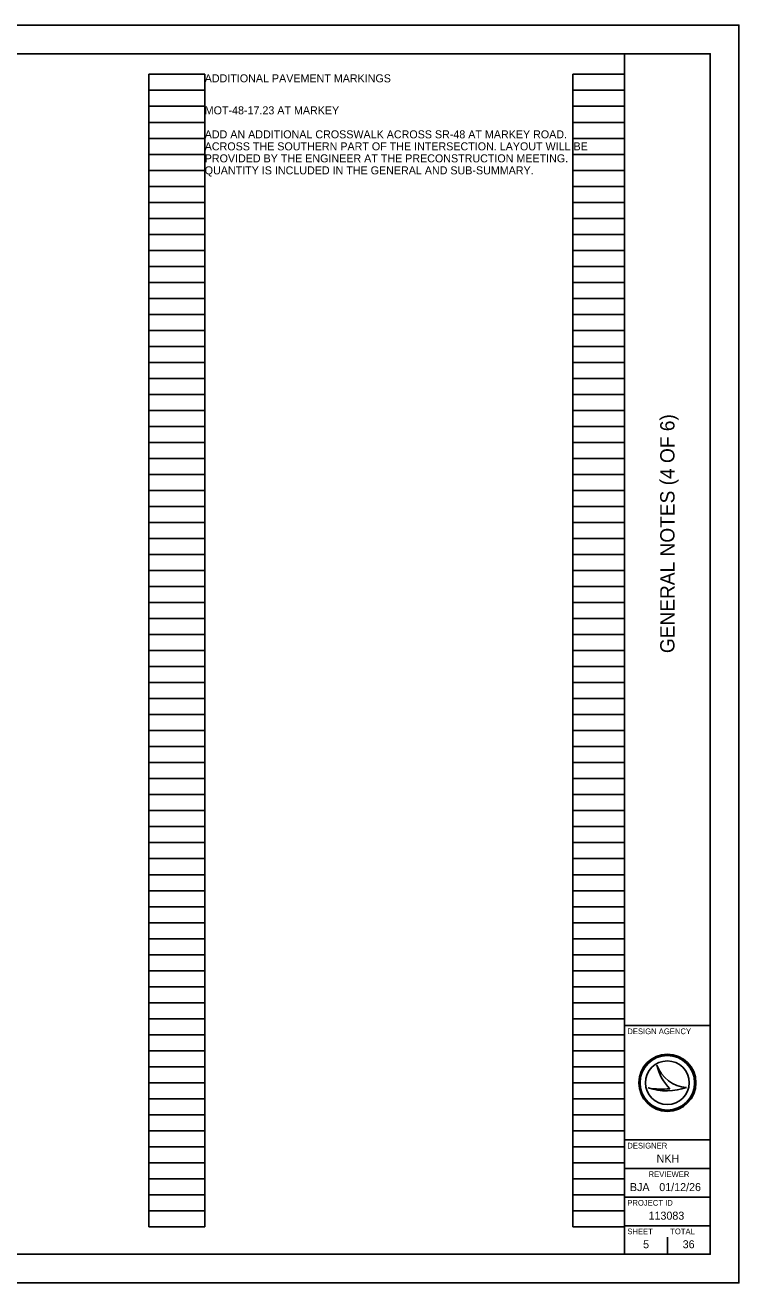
# Model space of a CAD drawing. Extents: x -27.4 to 34, y 0 to 22.
# Drawn here: x 21.52 to 34, y 0 to 22 of the extents above; entities that cross this region are included whole.
import ezdxf

# ---------------------------------------------------------------- set-up
doc = ezdxf.new("R2010")
doc.units = 0
for name, color, linetype in [('Default', 7, 'Continuous'), ('SH_Border', 7, 'Continuous'), ('SH_Cut_Line', 7, 'Continuous'), ('SH_Data', 7, 'Continuous')]:
    doc.layers.add(name, color=color, linetype=linetype)

msp = doc.modelspace()

# ---------------------------------------------------------------- linework, layer by layer
at = {"layer": 'Default'}
msp.add_line((1.5, 21.5), (24.949, 21.5), dxfattribs=at)
at = {"layer": 'SH_Border'}
for p, q in [((32, 0.5), (32, 21.5)), ((32, 4.5), (33.5, 4.5)), ((32, 2.5), (33.5, 2.5)), ((32, 2), (33.5, 2)), ((32, 1.5), (33.5, 1.5)), ((32, 1), (33.5, 1))]:
    msp.add_line(p, q, dxfattribs=at)
msp.add_lwpolyline([(1.5, 21.5), (33.5, 21.5), (33.5, 0.5), (1.5, 0.5)], close=True, dxfattribs=at)
at = {"layer": 'SH_Cut_Line'}
msp.add_lwpolyline([(0, 0), (34, 0), (34, 22), (0, 22)], close=True, dxfattribs=at)
at = {"layer": 'SH_Data'}
for p, q in [((23.68, 0.98), (23.68, 21.14)), ((23.68, 21.14), (24.66, 21.14)), ((24.66, 0.98), (24.66, 21.14)), ((31.1, 0.98), (31.1, 21.14)), ((31.1, 21.14), (32, 21.14)), ((32, 0.98), (32, 21.14)), ((23.68, 20.86), (24.66, 20.86)), ((31.1, 20.86), (32, 20.86)), ((23.68, 20.58), (24.66, 20.58)), ((31.1, 20.58), (32, 20.58)), ((23.68, 20.3), (24.66, 20.3)), ((31.1, 20.3), (32, 20.3)), ((23.68, 20.02), (24.66, 20.02)), ((31.1, 20.02), (32, 20.02)), ((23.68, 19.74), (24.66, 19.74)), ((31.1, 19.74), (32, 19.74)), ((23.68, 19.46), (24.66, 19.46)), ((31.1, 19.46), (32, 19.46)), ((23.68, 19.18), (24.66, 19.18)), ((31.1, 19.18), (32, 19.18)), ((23.68, 18.9), (24.66, 18.9)), ((31.1, 18.9), (32, 18.9)), ((23.68, 18.62), (24.66, 18.62)), ((31.1, 18.62), (32, 18.62)), ((23.68, 18.34), (24.66, 18.34)), ((31.1, 18.34), (32, 18.34)), ((23.68, 18.06), (24.66, 18.06)), ((31.1, 18.06), (32, 18.06)), ((23.68, 17.78), (24.66, 17.78)), ((31.1, 17.78), (32, 17.78)), ((23.68, 17.5), (24.66, 17.5)), ((31.1, 17.5), (32, 17.5)), ((23.68, 17.22), (24.66, 17.22)), ((31.1, 17.22), (32, 17.22)), ((23.68, 16.94), (24.66, 16.94)), ((31.1, 16.94), (32, 16.94)), ((23.68, 16.66), (24.66, 16.66)), ((31.1, 16.66), (32, 16.66)), ((23.68, 16.38), (24.66, 16.38)), ((31.1, 16.38), (32, 16.38)), ((23.68, 16.1), (24.66, 16.1)), ((31.1, 16.1), (32, 16.1)), ((23.68, 15.82), (24.66, 15.82)), ((31.1, 15.82), (32, 15.82)), ((23.68, 15.54), (24.66, 15.54)), ((31.1, 15.54), (32, 15.54)), ((23.68, 15.26), (24.66, 15.26)), ((31.1, 15.26), (32, 15.26)), ((23.68, 14.98), (24.66, 14.98)), ((31.1, 14.98), (32, 14.98)), ((23.68, 14.7), (24.66, 14.7)), ((31.1, 14.7), (32, 14.7)), ((23.68, 14.42), (24.66, 14.42)), ((31.1, 14.42), (32, 14.42)), ((23.68, 14.14), (24.66, 14.14)), ((31.1, 14.14), (32, 14.14)), ((23.68, 13.86), (24.66, 13.86)), ((31.1, 13.86), (32, 13.86)), ((23.68, 13.58), (24.66, 13.58)), ((31.1, 13.58), (32, 13.58)), ((23.68, 13.3), (24.66, 13.3)), ((31.1, 13.3), (32, 13.3)), ((23.68, 13.02), (24.66, 13.02)), ((31.1, 13.02), (32, 13.02)), ((23.68, 12.74), (24.66, 12.74)), ((31.1, 12.74), (32, 12.74)), ((23.68, 12.46), (24.66, 12.46)), ((31.1, 12.46), (32, 12.46)), ((23.68, 12.18), (24.66, 12.18)), ((31.1, 12.18), (32, 12.18)), ((23.68, 11.9), (24.66, 11.9)), ((31.1, 11.9), (32, 11.9)), ((23.68, 11.62), (24.66, 11.62)), ((31.1, 11.62), (32, 11.62)), ((23.68, 11.34), (24.66, 11.34)), ((31.1, 11.34), (32, 11.34)), ((23.68, 11.06), (24.66, 11.06)), ((31.1, 11.06), (32, 11.06)), ((23.68, 10.78), (24.66, 10.78)), ((31.1, 10.78), (32, 10.78)), ((23.68, 10.5), (24.66, 10.5)), ((31.1, 10.5), (32, 10.5)), ((23.68, 10.22), (24.66, 10.22)), ((31.1, 10.22), (32, 10.22)), ((23.68, 9.94), (24.66, 9.94)), ((31.1, 9.94), (32, 9.94)), ((23.68, 9.66), (24.66, 9.66)), ((31.1, 9.66), (32, 9.66)), ((23.68, 9.38), (24.66, 9.38)), ((31.1, 9.38), (32, 9.38)), ((23.68, 9.1), (24.66, 9.1)), ((31.1, 9.1), (32, 9.1)), ((23.68, 8.82), (24.66, 8.82)), ((31.1, 8.82), (32, 8.82)), ((23.68, 8.54), (24.66, 8.54)), ((31.1, 8.54), (32, 8.54)), ((23.68, 8.26), (24.66, 8.26)), ((31.1, 8.26), (32, 8.26)), ((23.68, 7.98), (24.66, 7.98)), ((31.1, 7.98), (32, 7.98)), ((23.68, 7.7), (24.66, 7.7)), ((31.1, 7.7), (32, 7.7)), ((23.68, 7.42), (24.66, 7.42)), ((31.1, 7.42), (32, 7.42)), ((23.68, 7.14), (24.66, 7.14)), ((31.1, 7.14), (32, 7.14)), ((23.68, 6.86), (24.66, 6.86)), ((31.1, 6.86), (32, 6.86)), ((23.68, 6.58), (24.66, 6.58)), ((31.1, 6.58), (32, 6.58)), ((23.68, 6.3), (24.66, 6.3)), ((31.1, 6.3), (32, 6.3)), ((23.68, 6.02), (24.66, 6.02)), ((31.1, 6.02), (32, 6.02)), ((23.68, 5.74), (24.66, 5.74)), ((31.1, 5.74), (32, 5.74)), ((23.68, 5.46), (24.66, 5.46)), ((31.1, 5.46), (32, 5.46)), ((23.68, 5.18), (24.66, 5.18)), ((31.1, 5.18), (32, 5.18)), ((23.68, 4.9), (24.66, 4.9)), ((31.1, 4.9), (32, 4.9)), ((23.68, 4.62), (24.66, 4.62)), ((31.1, 4.62), (32, 4.62)), ((23.68, 4.34), (24.66, 4.34)), ((31.1, 4.34), (32, 4.34)), ((23.68, 4.06), (24.66, 4.06)), ((31.1, 4.06), (32, 4.06)), ((23.68, 3.78), (24.66, 3.78)), ((31.1, 3.78), (32, 3.78)), ((32.567, 3.81), (32.567, 3.81)), ((23.68, 3.5), (24.66, 3.5)), ((31.1, 3.5), (32, 3.5)), ((32.417, 3.41), (32.417, 3.41)), ((32.75, 3.5), (32.75, 3.5)), ((33.087, 3.419), (33.087, 3.419)), ((23.68, 3.22), (24.66, 3.22)), ((31.1, 3.22), (32, 3.22)), ((23.68, 2.94), (24.66, 2.94)), ((31.1, 2.94), (32, 2.94)), ((23.68, 2.66), (24.66, 2.66)), ((31.1, 2.66), (32, 2.66)), ((23.68, 2.38), (24.66, 2.38)), ((31.1, 2.38), (32, 2.38)), ((23.68, 2.1), (24.66, 2.1)), ((31.1, 2.1), (32, 2.1)), ((23.68, 1.82), (24.66, 1.82)), ((31.1, 1.82), (32, 1.82)), ((23.68, 1.54), (24.66, 1.54)), ((31.1, 1.54), (32, 1.54)), ((23.68, 1.26), (24.66, 1.26)), ((31.1, 1.26), (32, 1.26)), ((23.68, 0.98), (24.66, 0.98)), ((31.1, 0.98), (32, 0.98)), ((32.375, 0.675), (32.375, 0.675)), ((32.75, 0.5), (32.75, 0.8))]:
    msp.add_line(p, q, dxfattribs=at)
for radius in [0.5, 0.477, 0.477, 0.382]:
    msp.add_circle((32.75, 3.5), radius, dxfattribs=at)
for centre, radius, start, end in [((33.116, 3.998), 0.58, 198.9257, 198.9319), ((33.347, 3.97), 0.796, 191.6379, 191.6421), ((33.116, 3.998), 0.58, 198.9319, 267.1657), ((33.347, 3.97), 0.796, 191.6421, 226.0947), ((32.739, 4.37), 1.013, 251.4576, 290.0832), ((32.648, 4.654), 1.266, 259.4964, 259.4995), ((32.739, 4.37), 1.013, 251.4527, 251.4576), ((32.648, 4.654), 1.266, 259.4995, 276.6672)]:
    msp.add_arc(centre, radius, start, end, dxfattribs=at)

# ---------------------------------------------------------------- texts
at = {"layer": 'Default'}
for s, p in [('ADDITIONAL PAVEMENT MARKINGS', (24.66, 21)), ('MOT-48-17.23 AT MARKEY', (24.66, 20.44)), ('ADD AN ADDITIONAL CROSSWALK ACROSS SR-48 AT MARKEY ROAD. ', (24.66, 20.02)), ('ACROSS THE SOUTHERN PART OF THE INTERSECTION. LAYOUT WILL BE ', (24.66, 19.81)), ('PROVIDED BY THE ENGINEER AT THE PRECONSTRUCTION MEETING. ', (24.66, 19.6)), ('QUANTITY IS INCLUDED IN THE GENERAL AND SUB-SUMMARY.', (24.66, 19.39))]:
    msp.add_text(s, height=0.14, dxfattribs=at).set_placement(p)
at = {"layer": 'SH_Data'}
msp.add_text('GENERAL NOTES (4 OF 6)', height=0.25, rotation=90, dxfattribs=at).set_placement((32.875, 11.015))
for s, height, p in [('DESIGN AGENCY', 0.1, (32.05, 4.35)), ('DESIGNER', 0.1, (32.05, 2.35)), ('NKH', 0.14, (32.562, 2.105)), ('REVIEWER', 0.1, (32.422, 1.85)), ('BJA', 0.14, (32.095, 1.605)), ('01/12/26', 0.14, (32.609, 1.605)), ('PROJECT ID', 0.1, (32.05, 1.35)), ('113083', 0.14, (32.421, 1.105)), ('SHEET', 0.1, (32.05, 0.85)), ('TOTAL', 0.1, (32.8, 0.85)), ('5', 0.14, (32.326, 0.605)), ('36', 0.14, (33.018, 0.605))]:
    msp.add_text(s, height=height, dxfattribs=at).set_placement(p)

doc.saveas('drawing.dxf')
